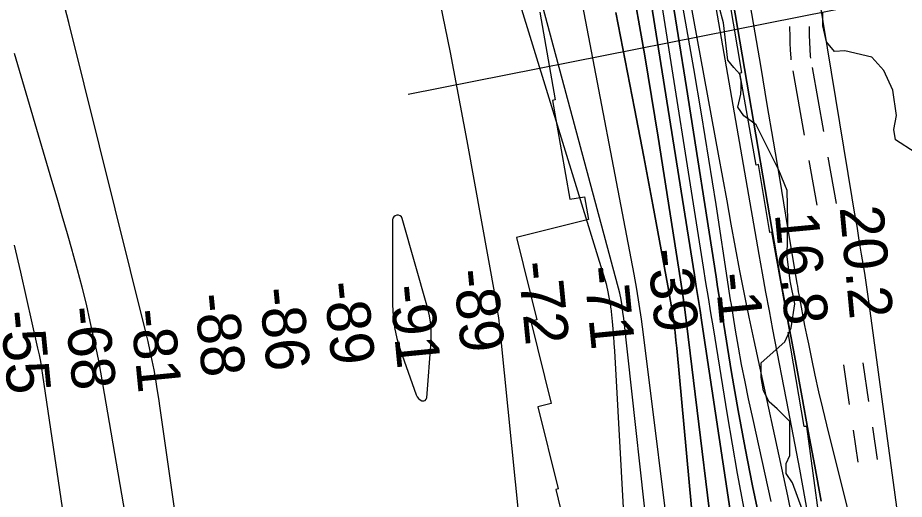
# Model space of a CAD drawing. Extents: x 3540316 to 3578335, y 553172 to 578787.
# Drawn here: x 3552828 to 3554191, y 559469 to 560208 of the extents above; entities that cross this region are included whole.
import ezdxf

# ---------------------------------------------------------------- set-up
doc = ezdxf.new("R2010")
doc.units = 0
for name, color, linetype in [('V-RIVR-EDGE', 7, 'Continuous'), ('V-RIVR-RANG', 7, 'Continuous'), ('V-ROAD-CNTR', 7, 'Continuous'), ('V-RRAP-RVMT', 7, 'Continuous'), ('V-SITE-VEGE', 7, 'Continuous'), ('V-TOPO-DPTH', 7, 'Continuous'), ('V-TOPO-MAJR', 7, 'Continuous'), ('V-TOPO-MINR', 7, 'Continuous'), ('V-TOPO-WATR', 7, 'Continuous')]:
    doc.layers.add(name, color=color, linetype=linetype)

msp = doc.modelspace()

# ---------------------------------------------------------------- linework, layer by layer
at = {"layer": 'V-RIVR-EDGE'}
msp.add_lwpolyline([(3554034.5, 559451.9), (3554019.2, 559493.6), (3554009.5, 559508.3), (3554009.5, 559523.6), (3554015.1, 559535.9), (3554015.2, 559588), (3553995.6, 559607.6), (3553983.4, 559618.1), (3553974.9, 559635.2), (3553971.2, 559655.5), (3553971.3, 559678.1), (3554007.5, 559710.5), (3554017.4, 559731.9), (3554023, 559768.7), (3554015.7, 559804.2), (3554010.9, 559841.6), (3554012.3, 559896.2), (3554011.2, 559942.7), (3553998.4, 559974), (3553963.6, 560044), (3553944.7, 560057.5), (3553935.5, 560071), (3553939.8, 560091.2), (3553940.5, 560099.8), (3553940.5, 560110.8), (3553938.1, 560121.8), (3553928.9, 560131.7), (3553919.7, 560143.3), (3553913.1, 560200.3), (3553899.8, 560250)], dxfattribs=at)
at = {"layer": 'V-RIVR-RANG'}
msp.add_line((3555056.5, 560414.5), (3553428.5, 560090.2), dxfattribs=at)
at = {"layer": 'V-ROAD-CNTR'}
for points in [[(3554017.4, 560143.7), (3554017.2, 560146.9), (3554016.4, 560158.3), (3554015.9, 560169.7), (3554015.6, 560180.9), (3554015.4, 560192.3), (3554015.4, 560195)], [(3554047.3, 560146.3), (3554047.1, 560149.2), (3554046.4, 560160), (3554045.9, 560170.8), (3554045.6, 560181.6), (3554045.4, 560192.5), (3554045.4, 560194.9)], [(3554067.4, 560033.4), (3554050, 560131.9)], [(3554037.9, 560028.2), (3554020.4, 560126.6)], [(3554087.1, 559923.1), (3554074.4, 559994)], [(3554057.1, 559920.2), (3554044.9, 559988.8)], [(3554107.1, 559614.4), (3554098.1, 559674.9)], [(3554136.8, 559618.8), (3554127.9, 559678.4)], [(3554120.4, 559525.4), (3554113, 559574.8)], [(3554150, 559529.8), (3554142.7, 559579.2)]]:
    msp.add_lwpolyline(points, dxfattribs=at)
at = {"layer": 'V-RRAP-RVMT'}
for p, q in [((3553941.3, 560124.4), (3553917, 560268.1)), ((3553630.8, 560216.8), (3553654.6, 560082.2)), ((3553938.2, 560123.5), (3553941.3, 560124.4)), ((3553963.5, 559981.8), (3553938.2, 560123.5)), ((3553654.6, 560082.2), (3553650.2, 560081.1)), ((3553650.2, 560081.1), (3553676.9, 559929.5)), ((3553967.2, 559982.7), (3553963.5, 559981.8)), ((3553984.6, 559878.4), (3553967.2, 559982.7)), ((3553676.9, 559929.5), (3553699.5, 559933.2)), ((3553699.5, 559933.2), (3553705.8, 559898.2)), ((3553705.8, 559898.2), (3553595, 559870.6)), ((3553987.5, 559878.9), (3553984.6, 559878.4)), ((3554015.3, 559725.6), (3553987.5, 559878.9)), ((3553595, 559870.6), (3553626.4, 559744.4)), ((3553626.4, 559744.4), (3553616.7, 559742)), ((3553616.7, 559742), (3553648.1, 559615.9)), ((3554012.5, 559725), (3554015.3, 559725.6)), ((3554037, 559580.2), (3554012.5, 559725)), ((3553648.1, 559615.9), (3553627.8, 559610.8)), ((3553627.8, 559610.8), (3553659.2, 559484.7)), ((3554041.3, 559580.4), (3554037, 559580.2)), ((3554078.5, 559304.3), (3554041.3, 559580.4)), ((3553659.2, 559484.7), (3553655.3, 559483.7)), ((3553655.3, 559483.7), (3553686.7, 559357.6))]:
    msp.add_line(p, q, dxfattribs=at)
at = {"layer": 'V-SITE-VEGE'}
msp.add_lwpolyline([(3554208.1, 560001.4), (3554177.9, 560020.6), (3554175.2, 560036.8), (3554179.3, 560058.4), (3554173.8, 560097.1), (3554159.6, 560127.4), (3554141.2, 560147.7), (3554099.8, 560157.4), (3554084.1, 560156.7), (3554071.6, 560171.2), (3554065.9, 560195.7), (3554066.1, 560216.8)], dxfattribs=at)
at = {"layer": 'V-TOPO-DPTH'}
for points in [[(3553286.1, 561921.5), (3553671.1, 561016.9), (3553679.5, 560979.3), (3553687.4, 560941.5), (3553694.4, 560903.6), (3553700.9, 560865.5), (3553868.5, 559813.6), (3553871.4, 559795.3), (3553874.3, 559776.9), (3553877.1, 559758.6), (3553879.9, 559740.2), (3553927.6, 559424.1), (3553940.9, 559335.2), (3553954.2, 559246.3), (3553967.3, 559157.4), (3553980.4, 559068.5), (3554000.6, 558930.6), (3554003.4, 558910.6), (3554006, 558890.5), (3554008.4, 558870.4), (3554010.6, 558850.4), (3554032, 558646.6)], [(3554032, 558646.6), (3554010.6, 558850.4), (3554008.4, 558870.4), (3554006, 558890.5), (3554003.4, 558910.6), (3554000.6, 558930.6), (3553980.4, 559068.5), (3553967.3, 559157.4), (3553954.2, 559246.3), (3553940.9, 559335.2), (3553927.6, 559424.1), (3553879.9, 559740.2), (3553877.1, 559758.6), (3553874.3, 559776.9), (3553871.4, 559795.3), (3553868.5, 559813.6), (3553700.9, 560865.5), (3553694.4, 560903.6), (3553687.4, 560941.5), (3553679.5, 560979.3), (3553671.1, 561016.9), (3553286.1, 561921.5)], [(3554134.8, 558647.4), (3554115.8, 558852.5), (3554113.5, 558875.3), (3554111, 558898.1), (3554108, 558920.8), (3554104.7, 558943.5), (3554082.4, 559090.7), (3554066.9, 559186.9), (3554050.2, 559282.8), (3554031.7, 559378.3), (3554012, 559473.7), (3553960.3, 559712.4), (3553952.8, 559748.1), (3553945.5, 559783.8), (3553938.5, 559819.6), (3553931.7, 559855.4), (3553925.2, 559891.2), (3553918.6, 559927.1), (3553912, 559962.9), (3553905.4, 559998.8), (3553709.9, 561066)], [(3554134.8, 558647.4), (3554115.8, 558852.5), (3554113.5, 558875.3), (3554111, 558898.1), (3554108, 558920.8), (3554104.7, 558943.5), (3554082.4, 559090.7), (3554066.9, 559186.9), (3554050.2, 559282.8), (3554031.7, 559378.3), (3554012, 559473.7), (3553960.3, 559712.4), (3553952.8, 559748.1), (3553945.5, 559783.8), (3553938.5, 559819.6), (3553931.7, 559855.4), (3553925.2, 559891.2), (3553918.6, 559927.1), (3553912, 559962.9), (3553905.4, 559998.8), (3553709.9, 561066)], [(3553857.5, 560646.5), (3553998.3, 559821.7), (3554001.1, 559805.5), (3554003.9, 559789.4), (3554006.8, 559773.2), (3554009.8, 559757.1), (3554023.7, 559681.4), (3554033.7, 559627.4), (3554043.6, 559573.4), (3554053.5, 559519.4), (3554063.4, 559465.4)], [(3553770.3, 560274.5), (3553792.2, 560149.9), (3553812.7, 560025), (3553849.6, 559789.2), (3553850.7, 559782), (3553851.8, 559774.8), (3553852.7, 559767.5), (3553853.7, 559760.3), (3553912.5, 559277.5), (3553920.2, 559212.5), (3553927.6, 559147.4), (3553934.5, 559082.3), (3553941.1, 559017.1), (3553945.3, 558974), (3553949.5, 558930.4), (3553953.7, 558886.7), (3553957.8, 558843), (3553961.9, 558799.4), (3553966, 558754.6), (3553972, 558688.5), (3553975.8, 558646.2)], [(3553770.3, 560274.5), (3553792.2, 560149.9), (3553812.7, 560025), (3553849.6, 559789.2), (3553850.7, 559782), (3553851.8, 559774.8), (3553852.7, 559767.5), (3553853.7, 559760.3), (3553912.5, 559277.5), (3553920.2, 559212.5), (3553927.6, 559147.4), (3553934.5, 559082.3), (3553941.1, 559017.1), (3553945.3, 558974), (3553949.5, 558930.4), (3553953.7, 558886.7), (3553957.8, 558843), (3553961.9, 558799.4), (3553966, 558754.6), (3553972, 558688.5), (3553975.8, 558646.2)], [(3553970.2, 559431.2), (3553957.9, 559489), (3553946.3, 559546.9), (3553935.6, 559605.1), (3553925.6, 559663.3), (3553911.5, 559749.9), (3553909, 559765), (3553906.6, 559780), (3553904.2, 559795.1), (3553901.9, 559810.1), (3553856.5, 560101.1), (3553830.9, 560261.6)], [(3553830.9, 560261.6), (3553856.5, 560101.1), (3553901.9, 559810.1), (3553904.2, 559795.1), (3553906.6, 559780), (3553909, 559765), (3553911.5, 559749.9), (3553925.6, 559663.3), (3553935.6, 559605.1), (3553946.3, 559546.9), (3553957.9, 559489), (3553970.2, 559431.2)], [(3553937, 558645.9), (3553921.2, 558832.1), (3553919, 558857.3), (3553916.8, 558882.5), (3553914.5, 558907.7), (3553912.2, 558932.8), (3553841.2, 559700.7), (3553840, 559712.8), (3553838.7, 559724.8), (3553837.2, 559736.9), (3553835.6, 559748.9), (3553833.8, 559760.9), (3553831.9, 559772.9), (3553829.9, 559784.8), (3553827.7, 559796.7), (3553804.6, 559920.9), (3553790.7, 559994.8), (3553776.6, 560068.7), (3553762.2, 560142.6), (3553747.7, 560216.4)], [(3553747.7, 560216.4), (3553762.2, 560142.6), (3553776.6, 560068.7), (3553790.7, 559994.8), (3553804.6, 559920.9), (3553827.7, 559796.7), (3553829.9, 559784.8), (3553831.9, 559772.9), (3553833.8, 559760.9), (3553835.6, 559748.9), (3553837.2, 559736.9), (3553838.7, 559724.8), (3553840, 559712.8), (3553841.2, 559700.7), (3553912.2, 558932.8), (3553914.5, 558907.7), (3553916.8, 558882.5), (3553919, 558857.3), (3553921.2, 558832.1), (3553937, 558645.9)]]:
    msp.add_lwpolyline(points, dxfattribs=at)
at = {"layer": 'V-TOPO-MAJR'}
msp.add_lwpolyline([(3553904.4, 558645.6), (3553900.7, 558690.5), (3553886.3, 558860.7), (3553885.6, 558869.8), (3553884.8, 558878.8), (3553884, 558887.9), (3553883.1, 558897), (3553870.6, 559035.4), (3553863.1, 559113.7), (3553855.1, 559191.9), (3553846.2, 559270), (3553836.9, 559348), (3553790.2, 559721.9), (3553787.1, 559745.1), (3553783.7, 559768.2), (3553779.8, 559791.3), (3553775.6, 559814.3), (3553692.3, 560251.3)], dxfattribs=at)
at = {"layer": 'V-TOPO-MINR'}
for points in [[(3554032, 558646.6), (3554010.6, 558850.4), (3554008.4, 558870.4), (3554006, 558890.5), (3554003.4, 558910.6), (3554000.6, 558930.6), (3553980.4, 559068.5), (3553967.3, 559157.4), (3553954.2, 559246.3), (3553940.9, 559335.2), (3553927.6, 559424.1), (3553879.9, 559740.2), (3553877.1, 559758.6), (3553874.3, 559776.9), (3553871.4, 559795.3), (3553868.5, 559813.6), (3553700.9, 560865.5), (3553694.4, 560903.6), (3553687.4, 560941.5), (3553679.5, 560979.3), (3553671.1, 561016.9), (3553286.1, 561921.5)], [(3554252.7, 558921.5), (3554138.9, 559758.3), (3554137.9, 559765.6), (3554136.9, 559772.8), (3554135.9, 559780), (3554134.8, 559787.2), (3554133.7, 559794.4), (3554132.6, 559801.7), (3554131.4, 559808.9), (3554130.3, 559816.1), (3554125.5, 559845), (3554122, 559866.6), (3554118.5, 559888.2), (3554114.9, 559909.9), (3554111.3, 559931.5), (3553920.7, 561087.5)], [(3553986.6, 559465.2), (3553977.2, 559507.2), (3553967.9, 559549.3), (3553958.7, 559591.3), (3553951.8, 559622.9), (3553946.3, 559649.2), (3553941.1, 559675.6), (3553936.3, 559702), (3553931.8, 559728.5), (3553925.3, 559767.9), (3553924.2, 559774.8), (3553923.1, 559781.6), (3553922.1, 559788.5), (3553921, 559795.3), (3553901.7, 559921.3), (3553890.7, 559991.1), (3553879.3, 560060.8), (3553867.4, 560130.4), (3553855.2, 560200), (3553697.9, 561074.4)], [(3554111.9, 559422.7), (3554072.1, 559583.1), (3554065.9, 559608.3), (3554060, 559633.7), (3554054.4, 559659.1), (3554048.9, 559684.5), (3554044.2, 559707.4), (3554041.3, 559721.4), (3554038.5, 559735.5), (3554035.8, 559749.5), (3554033.1, 559763.5), (3554029.5, 559783.2), (3554028.7, 559787.4), (3554028, 559791.7), (3554027.3, 559795.9), (3554026.6, 559800.1), (3554009.2, 559905.1), (3553999.7, 559961.8), (3553990.2, 560018.5), (3553980.6, 560075.2), (3553970.9, 560131.9), (3553806.8, 561082.8)], [(3553395.1, 560895.2), (3553732.9, 559799.3), (3553734, 559794.5), (3553735, 559789.7), (3553739.3, 559765.8), (3553739.4, 559764.9), (3553739.7, 559763.1), (3553739.8, 559762.3), (3553742, 559741.6), (3553743.1, 559730.4), (3553744, 559719.2), (3553744.8, 559707.9), (3553745.6, 559696.7), (3553787.1, 558945.8), (3553789.2, 558908), (3553791.3, 558870.2), (3553793.5, 558832.4), (3553795.8, 558794.6), (3553801.3, 558703.5), (3553804.5, 558644.9)], [(3553951.5, 559418.3), (3553934.9, 559508.1), (3553919.4, 559598.1), (3553897.6, 559731.9), (3553893.8, 559755.2), (3553890.1, 559778.4), (3553886.3, 559801.7), (3553882.7, 559825), (3553746, 560688.1)], [(3554063.4, 559465.4), (3554053.5, 559519.4), (3554043.6, 559573.4), (3554033.7, 559627.4), (3554023.7, 559681.4), (3554009.8, 559757.1), (3554006.8, 559773.2), (3554003.9, 559789.4), (3554001.1, 559805.5), (3553998.3, 559821.7), (3553857.5, 560646.5)], [(3553187.5, 558640.1), (3553180.8, 558680.5), (3553177.2, 558702.9), (3553173.6, 558725.3), (3553170.2, 558747.7), (3553166.9, 558770.1), (3553161.6, 558806.1), (3553161, 558810.6), (3553160.3, 558815), (3553159.7, 558819.5), (3553159.1, 558824), (3553047.1, 559608.7), (3553044.9, 559623.3), (3553042.6, 559638), (3553040.2, 559652.6), (3553037.6, 559667.2), (3553034.8, 559681.7), (3553031.8, 559696.2), (3553028.6, 559710.7), (3553025.1, 559725.1), (3552906.5, 560201), (3552874.3, 560324.9), (3552840.4, 560448.4), (3552804.1, 560571.2)], [(3553865.4, 558645.3), (3553847.6, 558854.1), (3553846.7, 558864.5), (3553845.8, 558875), (3553845, 558885.4), (3553844.2, 558895.8), (3553833.3, 559033.7), (3553826.7, 559113.1), (3553819.6, 559192.4), (3553811.7, 559271.6), (3553803.3, 559350.8), (3553759.7, 559746.1), (3553758.5, 559755.9), (3553757.2, 559765.7), (3553755.7, 559775.5), (3553754, 559785.2), (3553553.8, 560528.6)], [(3554161.5, 558647.6), (3554160.1, 558659.9), (3554140.2, 558833.5), (3554136.2, 558866.7), (3554131.8, 558899.9), (3554127.1, 558933), (3554122, 558966.1), (3554077.8, 559241.4), (3554062.7, 559332.5), (3554047.1, 559423.6), (3554030.5, 559514.6), (3554013.3, 559605.4), (3553989.3, 559729.3), (3553983.8, 559758.1), (3553978.4, 559786.9), (3553973.2, 559815.8), (3553968, 559844.6), (3553861.8, 560454.3)], [(3553465.4, 560290.4), (3553492.7, 560155.1), (3553518.4, 560019.4), (3553562.4, 559776), (3553564.8, 559761.8), (3553567, 559747.5), (3553568.8, 559733.1), (3553570.4, 559718.8), (3553620.3, 559221.4), (3553625.7, 559160.8), (3553630.2, 559100.2), (3553633.5, 559039.4), (3553635.8, 558978.6), (3553637.3, 558928.6), (3553637.8, 558892.8), (3553637.9, 558856.9), (3553637.1, 558821.1), (3553635.8, 558785.3), (3553628.8, 558643.5)], [(3553975.8, 558646.2), (3553972, 558688.5), (3553966, 558754.6), (3553961.9, 558799.4), (3553957.8, 558843), (3553953.7, 558886.7), (3553949.5, 558930.4), (3553945.3, 558974), (3553941.1, 559017.1), (3553934.5, 559082.3), (3553927.6, 559147.4), (3553920.2, 559212.5), (3553912.5, 559277.5), (3553853.7, 559760.3), (3553852.7, 559767.5), (3553851.8, 559774.8), (3553850.7, 559782), (3553849.6, 559789.2), (3553812.7, 560025), (3553792.2, 560149.9), (3553770.3, 560274.5)], [(3553970.2, 559431.2), (3553957.9, 559489), (3553946.3, 559546.9), (3553935.6, 559605.1), (3553925.6, 559663.3), (3553911.5, 559749.9), (3553909, 559765), (3553906.6, 559780), (3553904.2, 559795.1), (3553901.9, 559810.1), (3553856.5, 560101.1), (3553830.9, 560261.6)], [(3553937, 558645.9), (3553921.2, 558832.1), (3553919, 558857.3), (3553916.8, 558882.5), (3553914.5, 558907.7), (3553912.2, 558932.8), (3553841.2, 559700.7), (3553840, 559712.8), (3553838.7, 559724.8), (3553837.2, 559736.9), (3553835.6, 559748.9), (3553833.8, 559760.9), (3553831.9, 559772.9), (3553829.9, 559784.8), (3553827.7, 559796.7), (3553804.6, 559920.9), (3553790.7, 559994.8), (3553776.6, 560068.7), (3553762.2, 560142.6), (3553747.7, 560216.4)], [(3553041.4, 559167), (3552953.1, 559678.7), (3552952.3, 559683.6), (3552951.3, 559688.6), (3552950.3, 559693.5), (3552949.3, 559698.4), (3552939.6, 559741.7), (3552933.5, 559768.2), (3552927, 559794.6), (3552920.1, 559820.9), (3552912.8, 559847.2), (3552912.2, 559849.3), (3552904.3, 559876.6), (3552896.4, 559903.8), (3552888.5, 559931), (3552880.5, 559958.2), (3552823.1, 560153.4)], [(3553416.1, 559904.2), (3553413.7, 559905.1), (3553410.9, 559905.3), (3553408.3, 559904.2), (3553406.2, 559902.7), (3553405, 559900.4), (3553404.4, 559897.7), (3553404.2, 559767.1), (3553405.1, 559749.7), (3553407.1, 559732.4), (3553410.9, 559715.5), (3553415.9, 559698.7), (3553440.5, 559629), (3553442, 559626), (3553444, 559623.4), (3553446.6, 559621.4), (3553449.6, 559619.9), (3553452.2, 559619.8), (3553454.4, 559620.4), (3553455.9, 559622.1), (3553456.9, 559624.6), (3553463.6, 559711.3), (3553463.9, 559724.5), (3553463.3, 559737.6), (3553461.3, 559750.5), (3553458.3, 559763.4), (3553419.3, 559899.9), (3553417.9, 559902.4), (3553416.1, 559904.2)], [(3552822.4, 559859.2), (3552832.4, 559817.3), (3552858.5, 559700.9), (3552860.7, 559690.5), (3552862.8, 559680.1), (3552864.6, 559669.6), (3552866.3, 559659), (3552948.9, 559099.4), (3552956.1, 559049.6), (3552963.1, 558999.8), (3552969.8, 558949.9), (3552976.2, 558899.9), (3552986.5, 558818.7), (3552987.6, 558809.3), (3552988.7, 558800), (3552989.7, 558790.7), (3552990.7, 558781.3), (3553004.9, 558638.7)]]:
    msp.add_lwpolyline(points, dxfattribs=at)
at = {"layer": 'V-TOPO-WATR'}
msp.add_lwpolyline([(3554134.8, 558647.4), (3554115.8, 558852.5), (3554113.5, 558875.3), (3554111, 558898.1), (3554108, 558920.8), (3554104.7, 558943.5), (3554082.4, 559090.7), (3554066.9, 559186.9), (3554050.2, 559282.8), (3554031.7, 559378.3), (3554012, 559473.7), (3553960.3, 559712.4), (3553952.8, 559748.1), (3553945.5, 559783.8), (3553938.5, 559819.6), (3553931.7, 559855.4), (3553925.2, 559891.2), (3553918.6, 559927.1), (3553912, 559962.9), (3553905.4, 559998.8), (3553709.9, 561066)], dxfattribs=at)

# ---------------------------------------------------------------- texts
at = {"layer": 'V-RIVR-RANG'}
for s, rotation, p in [('20.2', 275.3283, (3554091.6, 559917.1)), ('16.8', 275.3283, (3553992.1, 559907.5)), ('-39', 275.6107, (3553796, 559851.5)), ('-72', 275.6107, (3553597, 559832.2)), ('-89', 275.6107, (3553497.7, 559820.3)), ('-71', 275.6107, (3553698.1, 559825.2)), ('-1', 275.6107, (3553900.1, 559814.8)), ('-86', 275.6107, (3553199, 559792)), ('-89', 275.6107, (3553298.6, 559801.2)), ('-91', 275.6107, (3553399.6, 559796.1)), ('-88', 275.6107, (3553099.4, 559782.9)), ('-68', 275.6107, (3552900.4, 559762.8)), ('-55', 275.6107, (3552800.6, 559756.5)), ('-81', 275.6107, (3553001.3, 559759))]:
    msp.add_text(s, height=67, rotation=rotation, dxfattribs=at).set_placement(p)

doc.saveas('drawing.dxf')
